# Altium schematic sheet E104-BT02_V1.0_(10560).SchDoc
size A3; SheetNumber: 1; SheetTotal: 1
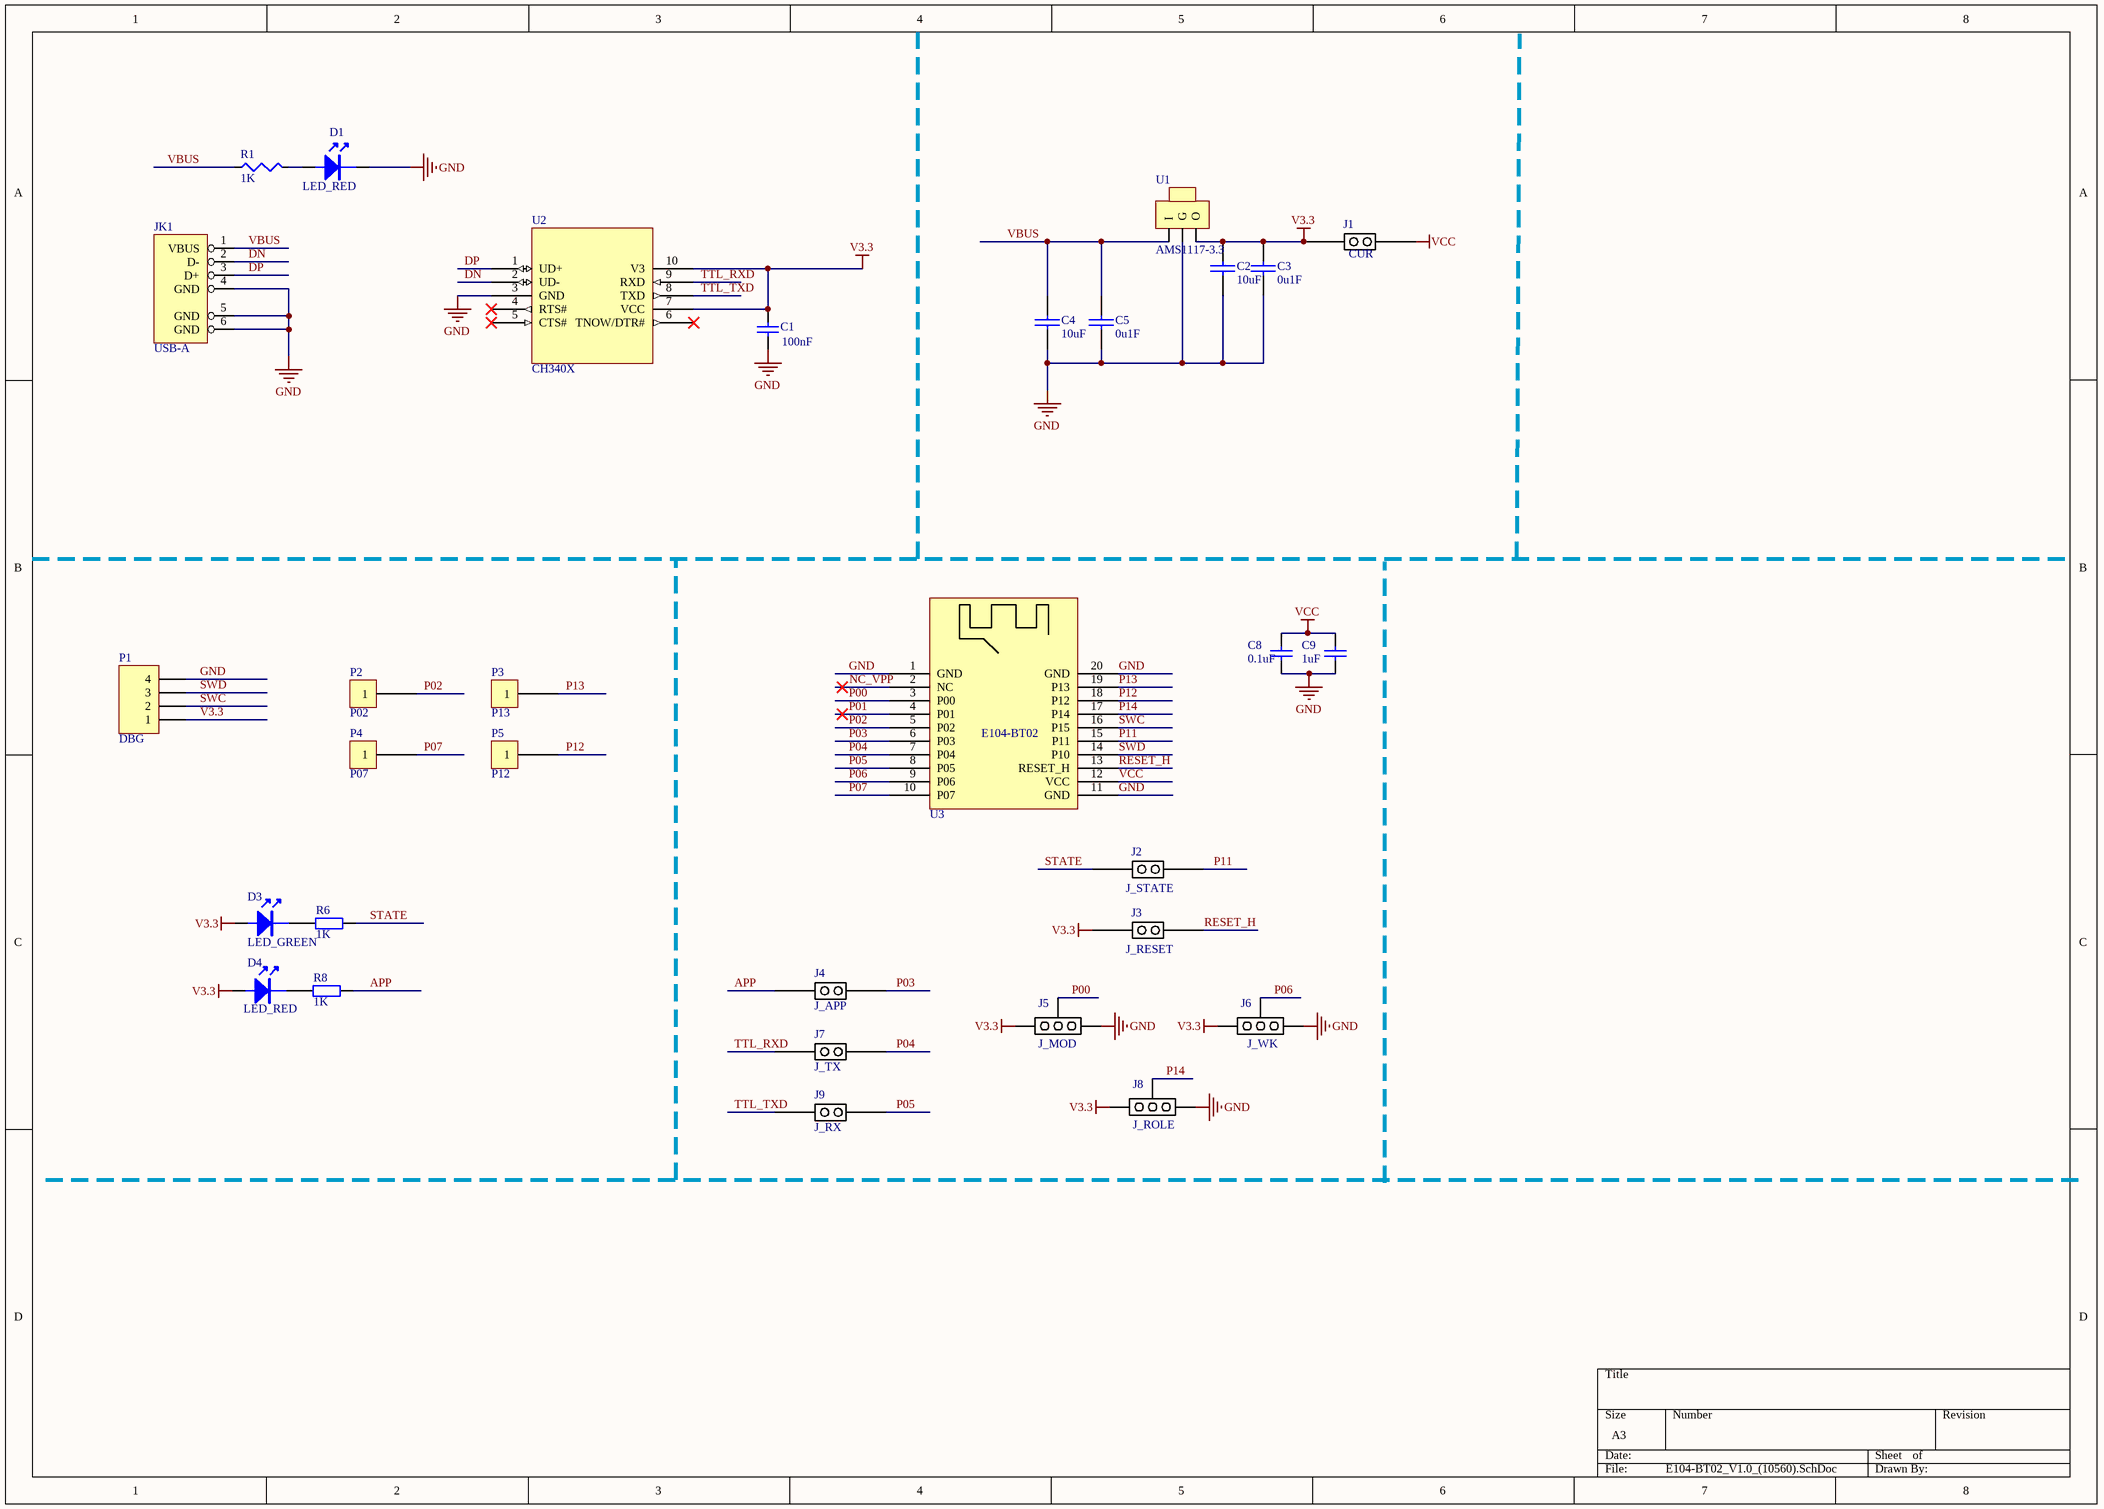
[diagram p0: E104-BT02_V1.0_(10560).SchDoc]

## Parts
C1  value 100nF  [E-CAP-0603]  (hidden comment: Cap)
C2  10uF  [E-CAP-0603]
C3  0u1F  [E-CAP-0603]
C4  10uF  [E-CAP-0603]
C5  0u1F  [E-CAP-0603]
C8  0.1uF  [E-CAP-0603]
C9  1uF  [E-CAP-0603]
D1  LED_RED  [E-LED-0805]
D3  LED_GREEN  [E-LED-0805]
D4  LED_RED  [E-LED-0805]
J1  CUR  [E-2P-2.54-1]
J2  J_STATE  [E-2P-2.54-1]
J3  J_RESET  [E-2P-2.54-1]
J4  J_APP  [E-2P-2.54-1]
J5  J_MOD  [E-3P-2.54-1]
J6  J_WK  [E-3P-2.54-1]
J7  J_TX  [E-2P-2.54-1]
J8  J_ROLE  [HDR1X3]
J9  J_RX  [E-2P-2.54-1]
JK1  USB-A  [USB-AG-DIP]
P1  DBG  [E-4P-2.54-1]
P2  P02  [E-1×1P-1]
P3  P13  [E-1×1P-1]
P4  P07  [E-1×1P-1]
P5  P12  [E-1×1P-1]
R1  1K  [E-RES-0603]
R6  1K  [E-RES-0603]
R8  1K  [E-RES-0603]
U1  AMS1117-3.3  [E-SOT-223]
U2  CH340X  [MSOP10]
U3  E104-BT02_V1.1  [E104-BT02_V1.1]  (value not drawn)

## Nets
GND: C1.1 C2.2 C3.2 C4.2 C5.2 C8.2 C9.2 D1.K J5.3 J6.3 J8.3 JK1.4(GND) JK1.5(GND) JK1.6(GND) P1.4 U1.1(G) U2.3(GND) U3.1(GND) U3.11(GND) U3.20(GND)
V3.3: C1.2 C2.1 C3.1 D3.A D4.A J1.1 J3.1 J5.1 J6.1 J8.1 P1.1 U1.2(O) U2.7(VCC) U2.10(V3)
VCC: C8.1 C9.1 J1.2 U3.12(VCC)
APP: J4.1 R8.1
DN: JK1.2(D-) U2.2(UD-)
DP: JK1.3(D+) U2.1(UD+)
NC_VPP: U3.2(NC)
P00: J5.2 U3.3(P00)
P01: U3.4(P01)
P02: P2.1 U3.5(P02)
P03: J4.2 U3.6(P03)
P04: J7.2 U3.7(P04)
P05: J9.2 U3.8(P05)
P06: J6.2 U3.9(P06)
P07: P4.1 U3.10(P07)
P11: J2.2 U3.15(P11)
P12: P5.1 U3.18(P12)
P13: P3.1 U3.19(P13)
P14: J8.2 U3.17(P14)
RESET_H: J3.2 U3.13(RESET_H)
STATE: J2.1 R6.1
SWC: P1.2 U3.16(P15)
SWD: P1.3 U3.14(P10)
TTL_RXD: J7.1 U2.9(RXD)
TTL_TXD: J9.1 U2.8(TXD)
VBUS: C4.1 C5.1 JK1.1(VBUS) R1.1 U1.3(I)
NetD1_A: D1.A R1.2
NetD3_K: D3.K R6.2
NetD4_K: D4.K R8.2

Not connected (* = marked no-connect by the designer): U2 4(RTS#)* 5(CTS#)* 6(TNOW/DTR#)*

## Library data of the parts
C1 = Cap: Capacitor
C2-C5 = cap0603: 0603
C8 C9 = Cap: 0603; Value: 0.01uF
D1 D3 D4 = LED: 0805
J1-J4 J7 J9 = JMP2: HDR1X2
J5 J6 J8 = JMP3: HDR1X3
JK1 = USB-A: USB-AG-DIP
P1 = Header 4H: HDR1X4
P2-P5 = Header 1H: HDR1X1
R1 = res0603: 0603
R6 R8 = Res2: 0603; Value: 4K7
U1 = AMS1117-3.3: SOT-223
U2 = CH340X: USB to TTL Serial / UART
U3 = E104-BT02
